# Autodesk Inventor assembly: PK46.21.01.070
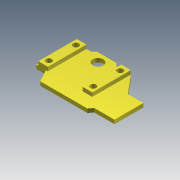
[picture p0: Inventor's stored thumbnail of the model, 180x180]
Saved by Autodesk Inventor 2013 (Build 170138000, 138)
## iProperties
Created: 2005-04
Part Number: PK46.21.01.070
Document SubType Name: Assembly
Designer: salex
Manufacturer: Standard
Standards Organization: Custom
Author: salex
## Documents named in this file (3)
- C:\Product Design Suite 2013\Data\Assy, Chassis, Front\PK46.21.01.070.iam
- C:\Product Design Suite 2013\Data\Assy, Chassis, Front\PK46.21.01.017.ipt
- C:\Product Design Suite 2013\Data\Assy, Chassis, Front\PK46.21.01.018.ipt
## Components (3 placed, 2 different names)
1. PK46.21.01.017:1 — Insert:1, Insert:2, Mate:1, Mate:2
2. PK46.21.01.018:1 — Insert:1, Mate:1
3. PK46.21.01.018:2 — Insert:2, Mate:2
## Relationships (4: Insert 2, Mate 2)
- Insert:1: PK46.21.01.017:1 ↔ PK46.21.01.018:1
- Insert:2: PK46.21.01.017:1 ↔ PK46.21.01.018:2
- Mate:1: PK46.21.01.017:1 ↔ PK46.21.01.018:1
- Mate:2: PK46.21.01.017:1 ↔ PK46.21.01.018:2
